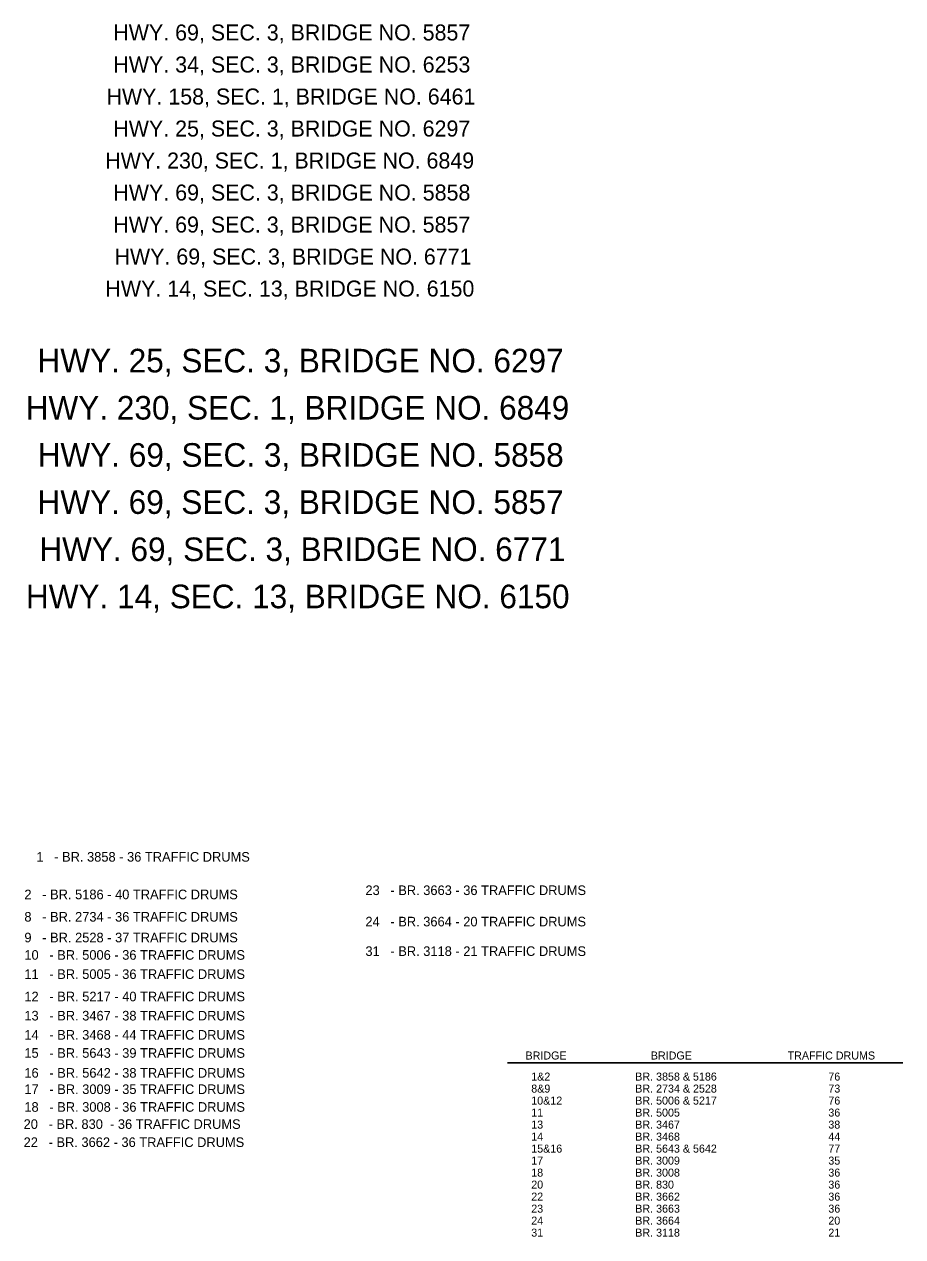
# Model space of a CAD drawing. Extents: x 1930579 to 1939784, y 596179 to 597522.
# Drawn here: x 1939126 to 1939784, y 596179 to 597088 of the extents above; entities that cross this region are included whole.
import ezdxf

# ---------------------------------------------------------------- set-up
doc = ezdxf.new("R2010")
doc.units = 0
doc.layers.add('Default', color=7, linetype='Continuous')
doc.layers.add('R_Annotation', color=7, linetype='Continuous')

msp = doc.modelspace()

# ---------------------------------------------------------------- linework, layer by layer
at = {"layer": 'R_Annotation'}
msp.add_line((1939487.5, 596309.64), (1939783.79, 596309.64), dxfattribs=at)

# ---------------------------------------------------------------- texts
at = {"layer": 'Default'}
for s, height, p in [('HWY. 69, SEC. 3, BRIDGE NO. 5857', 12, (1939192.2, 597076.08)), ('HWY. 34, SEC. 3, BRIDGE NO. 6253', 12, (1939192.23, 597052.08)), ('HWY. 158, SEC. 1, BRIDGE NO. 6461', 12, (1939187.11, 597028.08)), ('HWY. 25, SEC. 3, BRIDGE NO. 6297', 12, (1939192.2, 597004.08)), ('HWY. 230, SEC. 1, BRIDGE NO. 6849', 12, (1939186.18, 596980.08)), ('HWY. 69, SEC. 3, BRIDGE NO. 5858', 12, (1939192.26, 596956.08)), ('HWY. 69, SEC. 3, BRIDGE NO. 5857', 12, (1939192.2, 596932.08)), ('HWY. 69, SEC. 3, BRIDGE NO. 6771', 12, (1939193.11, 596908.08)), ('HWY. 14, SEC. 13, BRIDGE NO. 6150', 12, (1939186.31, 596884.08)), ('HWY. 25, SEC. 3, BRIDGE NO. 6297', 17.6819, (1939135.45, 596827.23)), ('HWY. 230, SEC. 1, BRIDGE NO. 6849', 17.6819, (1939126.57, 596791.87)), ('HWY. 69, SEC. 3, BRIDGE NO. 5858', 17.6819, (1939135.53, 596756.5)), ('HWY. 69, SEC. 3, BRIDGE NO. 5857', 17.6819, (1939135.45, 596721.14)), ('HWY. 69, SEC. 3, BRIDGE NO. 6771', 17.6819, (1939136.78, 596685.78)), ('HWY. 14, SEC. 13, BRIDGE NO. 6150', 17.6819, (1939126.77, 596650.41))]:
    msp.add_text(s, height=height, rotation=360, dxfattribs=at).set_placement(p)
at = {"layer": 'R_Annotation'}
for s, height, p in [('1   - BR. 3858 - 36 TRAFFIC DRUMS', 7.2, (1939134.58, 596460.44)), ('23   - BR. 3663 - 36 TRAFFIC DRUMS', 7.2, (1939381.15, 596435.39)), ('2   - BR. 5186 - 40 TRAFFIC DRUMS', 7.2, (1939125.59, 596432.25)), ('8   - BR. 2734 - 36 TRAFFIC DRUMS', 7.2, (1939125.59, 596415.48)), ('24   - BR. 3664 - 20 TRAFFIC DRUMS', 7.2, (1939381.15, 596411.88)), ('9   - BR. 2528 - 37 TRAFFIC DRUMS', 7.2, (1939125.59, 596399.93)), ('31   - BR. 3118 - 21 TRAFFIC DRUMS', 7.2, (1939381.15, 596389.72)), ('10   - BR. 5006 - 36 TRAFFIC DRUMS', 7.2, (1939125.59, 596386.88)), ('11   - BR. 5005 - 36 TRAFFIC DRUMS', 7.2, (1939125.59, 596372.5)), ('12   - BR. 5217 - 40 TRAFFIC DRUMS', 7.2, (1939125.59, 596355.72)), ('13   - BR. 3467 - 38 TRAFFIC DRUMS', 7.2, (1939125.59, 596341.35)), ('14   - BR. 3468 - 44 TRAFFIC DRUMS', 7.2, (1939125.59, 596326.97)), ('15   - BR. 5643 - 39 TRAFFIC DRUMS', 7.2, (1939125.59, 596313.39)), ('BRIDGE ', 6, (1939501.11, 596312.09)), ('BRIDGE ', 6, (1939595.01, 596312.09)), ('TRAFFIC DRUMS', 6, (1939697.54, 596312.09)), ('16   - BR. 5642 - 38 TRAFFIC DRUMS', 7.2, (1939125.59, 596298.47)), ('1&2', 6, (1939505.41, 596296.29)), ('BR. 3858 & 5186', 6, (1939583.36, 596296.29)), ('76', 6, (1939728.04, 596296.29)), ('17   - BR. 3009 - 35 TRAFFIC DRUMS', 7.2, (1939125.59, 596286.22)), ('8&9', 6, (1939505.41, 596287.29)), ('BR. 2734 & 2528', 6, (1939583.36, 596287.29)), ('73', 6, (1939728.04, 596287.29)), ('18   - BR. 3008 - 36 TRAFFIC DRUMS', 7.2, (1939125.59, 596272.91)), ('10&12', 6, (1939505.41, 596278.29)), ('BR. 5006 & 5217', 6, (1939583.36, 596278.29)), ('76', 6, (1939728.04, 596278.29)), ('11', 6, (1939505.41, 596269.29)), ('BR. 5005', 6, (1939583.36, 596269.29)), ('36', 6, (1939728.04, 596269.29)), ('20   - BR. 830  - 36 TRAFFIC DRUMS', 7.2, (1939125.02, 596260.06)), ('13', 6, (1939505.41, 596260.29)), ('BR. 3467', 6, (1939583.36, 596260.29)), ('38', 6, (1939728.04, 596260.29)), ('22   - BR. 3662 - 36 TRAFFIC DRUMS', 7.2, (1939125.02, 596246.48)), ('14', 6, (1939505.41, 596251.29)), ('BR. 3468', 6, (1939583.36, 596251.29)), ('44', 6, (1939728.04, 596251.29)), ('15&16', 6, (1939505.41, 596242.29)), ('BR. 5643 & 5642', 6, (1939583.36, 596242.29)), ('77', 6, (1939728.04, 596242.29)), ('17', 6, (1939505.41, 596233.29)), ('BR. 3009', 6, (1939583.36, 596233.29)), ('35', 6, (1939728.04, 596233.29)), ('18', 6, (1939505.41, 596224.29)), ('BR. 3008', 6, (1939583.36, 596224.29)), ('36', 6, (1939728.04, 596224.29)), ('20', 6, (1939505.41, 596215.29)), ('BR. 830', 6, (1939583.36, 596215.29)), ('36', 6, (1939728.04, 596215.29)), ('22', 6, (1939505.41, 596206.29)), ('BR. 3662', 6, (1939583.36, 596206.29)), ('36', 6, (1939728.04, 596206.29)), ('23', 6, (1939505.41, 596197.29)), ('BR. 3663', 6, (1939583.36, 596197.29)), ('36', 6, (1939728.04, 596197.29)), ('24', 6, (1939505.41, 596188.29)), ('BR. 3664', 6, (1939583.36, 596188.29)), ('20', 6, (1939728.04, 596188.29)), ('31', 6, (1939505.41, 596179.29)), ('BR. 3118', 6, (1939583.36, 596179.29)), ('21', 6, (1939728.04, 596179.29))]:
    msp.add_text(s, height=height, rotation=360, dxfattribs=at).set_placement(p)

doc.saveas('drawing.dxf')
